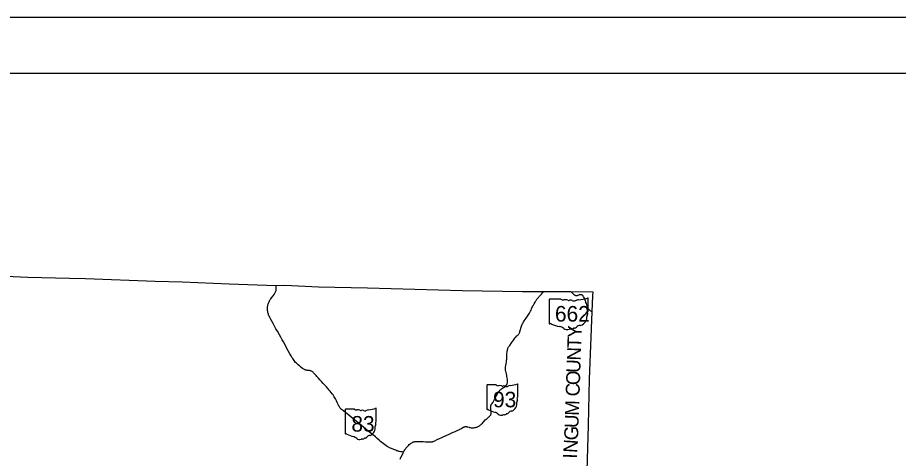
# Model space of a CAD drawing. Extents: x 1913970 to 2287843, y 78841 to 799733.
# Drawn here: x 2161112 to 2224478, y 768018 to 799733 of the extents above; entities that cross this region are included whole.
import ezdxf

# ---------------------------------------------------------------- set-up
doc = ezdxf.new("R2010")
doc.units = 0
for name, color, linetype in [('GM_X_County', 7, 'Continuous'), ('GM_X_County_Text', 7, 'Continuous'), ('GM_X_State_Location', 7, 'Continuous'), ('GM_X_State_Route', 7, 'Continuous'), ('GM_X_State_Shield', 7, 'Continuous'), ('SH_Border', 7, 'Continuous'), ('SH_Cut_Line', 7, 'Continuous')]:
    doc.layers.add(name, color=color, linetype=linetype)

msp = doc.modelspace()

# ---------------------------------------------------------------- linework, layer by layer
at = {"layer": 'GM_X_County'}
msp.add_lwpolyline([(2160255, 781127), (2161838, 781046), (2164851, 780995), (2165985, 780969), (2171000, 780768), (2172957, 780727), (2176338, 780588), (2179692, 780466), (2180329, 780472), (2182770, 780366), (2186293, 780295), (2193090, 780093), (2197442, 780016), (2198976, 780038), (2200924, 780017), (2202494, 779994), (2202479, 779737), (2202424, 778558), (2202231, 773716), (2202153, 770412), (2201913, 762197)], dxfattribs=at)
at = {"layer": 'GM_X_State_Route'}
for points in [[(2188873, 768462), (2188775, 768480), (2188678, 768496), (2188586, 768511), (2188581, 768512), (2188534, 768522), (2188487, 768535), (2188440, 768551), (2188395, 768569), (2188320, 768602), (2188254, 768630), (2188229, 768641), (2188122, 768683), (2187938, 768750), (2187877, 768775), (2187833, 768796), (2187790, 768820), (2187748, 768845), (2187694, 768881), (2187615, 768940), (2187421, 769090), (2187230, 769244), (2187128, 769327), (2186989, 769441), (2186851, 769558), (2186708, 769679), (2186701, 769685), (2186524, 769832), (2186423, 769915), (2186220, 770082), (2186016, 770247), (2185825, 770402), (2185649, 770549), (2185560, 770622), (2185484, 770684), (2185357, 770787), (2185229, 770891), (2185089, 771005), (2184950, 771119), (2184694, 771324), (2184552, 771435), (2184423, 771536), (2184387, 771569), (2184353, 771604), (2184321, 771641), (2184291, 771680), (2184264, 771721), (2184231, 771777), (2184192, 771849), (2184099, 772041), (2184042, 772159), (2183979, 772292), (2183941, 772365), (2183892, 772451), (2183841, 772535), (2183804, 772590), (2183765, 772643), (2183657, 772787), (2183606, 772852), (2183532, 772935), (2183450, 773024), (2183325, 773162), (2183194, 773303), (2183102, 773402), (2182973, 773544), (2182852, 773676), (2182750, 773792), (2182647, 773906), (2182582, 773978), (2182541, 774024), (2182464, 774106), (2182400, 774176), (2182364, 774212), (2182323, 774247), (2182292, 774272), (2182266, 774287), (2182240, 774300), (2182219, 774309), (2182190, 774319), (2182159, 774327), (2182119, 774334), (2182071, 774339), (2181993, 774346), (2181945, 774350), (2181897, 774357), (2181849, 774368), (2181818, 774378), (2181772, 774394), (2181742, 774407), (2181699, 774429), (2181657, 774454), (2181617, 774482), (2181579, 774513), (2181492, 774588), (2181391, 774672), (2181291, 774756), (2181240, 774802), (2181230, 774811), (2181171, 774867), (2181115, 774927), (2181061, 774989), (2181000, 775065), (2180951, 775131), (2180905, 775198), (2180852, 775281), (2180785, 775393), (2180697, 775550), (2180588, 775752), (2180465, 775983), (2180403, 776098), (2180237, 776398), (2180185, 776486), (2180145, 776554), (2180047, 776734), (2179951, 776904), (2179805, 777161), (2179801, 777168), (2179701, 777350), (2179498, 777716), (2179300, 778070), (2179252, 778156), (2179223, 778216), (2179196, 778276), (2179165, 778350), (2179150, 778397), (2179132, 778459), (2179116, 778523), (2179105, 778587), (2179097, 778652), (2179091, 778717), (2179088, 778783), (2179089, 778821), (2179092, 778884), (2179098, 778945), (2179107, 778994), (2179121, 779057), (2179138, 779121), (2179158, 779183), (2179181, 779244), (2179200, 779289), (2179229, 779348), (2179260, 779406), (2179293, 779462), (2179320, 779503), (2179368, 779569), (2179490, 779723), (2179560, 779814), (2179598, 779868), (2179625, 779909), (2179650, 779952), (2179671, 779997), (2179689, 780043), (2179702, 780091), (2179712, 780139), (2179719, 780188), (2179722, 780238), (2179722, 780287), (2179718, 780336), (2179714, 780382), (2179707, 780418), (2179693, 780463)], [(2188873, 768462), (2188923, 768551), (2188962, 768623), (2188986, 768666), (2189012, 768708), (2189031, 768735), (2189048, 768758), (2189056, 768767), (2189117, 768834), (2189184, 768906), (2189203, 768925), (2189231, 768953), (2189291, 769009), (2189353, 769063), (2189392, 769094), (2189432, 769122), (2189474, 769148), (2189517, 769173), (2189547, 769187), (2189578, 769199), (2189602, 769207), (2189625, 769214), (2189657, 769221), (2189690, 769226), (2189739, 769230), (2189789, 769231), (2189969, 769227), (2190117, 769224), (2190232, 769223), (2190298, 769222), (2190445, 769215), (2190543, 769211), (2190707, 769205), (2190805, 769203), (2190854, 769205), (2190903, 769209), (2190951, 769216), (2190983, 769224), (2191014, 769234), (2191059, 769252), (2191133, 769287), (2191294, 769369), (2191456, 769448), (2191575, 769503), (2191768, 769593), (2191949, 769672), (2192219, 769791), (2192309, 769831), (2192459, 769898), (2192482, 769908), (2192593, 769958), (2192774, 770037), (2192849, 770070), (2192893, 770090), (2192936, 770113), (2192993, 770146), (2193132, 770233), (2193176, 770258), (2193203, 770270), (2193226, 770279), (2193253, 770289), (2193284, 770296), (2193313, 770301), (2193331, 770303), (2193351, 770304), (2193385, 770304), (2193411, 770302), (2193432, 770299), (2193454, 770295), (2193499, 770283), (2193600, 770254), (2193630, 770248), (2193677, 770237), (2193737, 770228), (2193802, 770222), (2193851, 770220), (2193905, 770221), (2193946, 770223), (2193997, 770230), (2194044, 770240), (2194092, 770253), (2194138, 770269), (2194198, 770294), (2194242, 770314), (2194285, 770339), (2194331, 770367), (2194381, 770400), (2194419, 770430), (2194456, 770462), (2194492, 770495), (2194550, 770554), (2194682, 770700), (2194761, 770783), (2194820, 770840), (2194858, 770873), (2194909, 770914), (2194974, 770964), (2195021, 771004), (2195060, 771038), (2195092, 771071), (2195116, 771099), (2195134, 771123), (2195151, 771151), (2195162, 771175), (2195169, 771195), (2195179, 771226), (2195183, 771257), (2195185, 771286), (2195185, 771310), (2195183, 771342), (2195179, 771378), (2195166, 771453), (2195152, 771550), (2195148, 771599), (2195145, 771664), (2195147, 771713), (2195153, 771763), (2195159, 771795), (2195168, 771827), (2195179, 771858), (2195192, 771888), (2195208, 771917), (2195227, 771946), (2195248, 771974), (2195298, 772037), (2195328, 772074), (2195357, 772114), (2195383, 772156), (2195405, 772199), (2195425, 772244), (2195461, 772335), (2195485, 772392), (2195508, 772441), (2195537, 772499), (2195577, 772571), (2195682, 772757), (2195706, 772799), (2195724, 772826), (2195745, 772853), (2195777, 772890), (2195812, 772924), (2195852, 772957), (2195932, 773014), (2196064, 773111), (2196184, 773198), (2196220, 773229), (2196245, 773252), (2196267, 773275), (2196283, 773293), (2196293, 773307), (2196306, 773328), (2196320, 773357), (2196332, 773386), (2196342, 773417), (2196349, 773449), (2196353, 773481), (2196356, 773529), (2196356, 773578), (2196353, 773644), (2196345, 773725), (2196333, 773805), (2196316, 773913), (2196302, 773993), (2196277, 774105), (2196232, 774283), (2196224, 774330), (2196217, 774379), (2196212, 774429), (2196212, 774480), (2196212, 774543), (2196217, 774611), (2196230, 774692), (2196252, 774821), (2196278, 774966), (2196283, 775000), (2196287, 775030), (2196294, 775089), (2196298, 775146), (2196300, 775225), (2196305, 775469), (2196314, 775569), (2196322, 775650), (2196330, 775725), (2196346, 775816), (2196359, 775862), (2196372, 775910), (2196392, 775956), (2196414, 776001), (2196439, 776044), (2196469, 776090), (2196514, 776152), (2196640, 776323), (2196716, 776430), (2196781, 776525), (2196838, 776605), (2196877, 776658), (2196919, 776708), (2196953, 776744), (2197036, 776827), (2197083, 776871), (2197116, 776907), (2197136, 776932), (2197165, 776971), (2197192, 777013), (2197215, 777057), (2197235, 777100), (2197252, 777145), (2197276, 777224), (2197345, 777460), (2197366, 777523), (2197393, 777600), (2197416, 777660), (2197445, 777722), (2197474, 777779), (2197517, 777850), (2197562, 777921), (2197690, 778111), (2197839, 778325), (2197930, 778461), (2197964, 778517), (2197989, 778560), (2198016, 778618), (2198050, 778694), (2198083, 778769), (2198116, 778844), (2198149, 778917), (2198173, 778966), (2198188, 778994), (2198219, 779048), (2198264, 779128), (2198344, 779259), (2198397, 779344), (2198423, 779385), (2198477, 779466), (2198535, 779546), (2198578, 779599), (2198619, 779649), (2198696, 779732), (2198797, 779841), (2198871, 779924), (2198917, 779974), (2198977, 780035)], [(2202425, 778555), (2202388, 778576), (2202348, 778603), (2202322, 778624), (2202285, 778656), (2202255, 778689), (2202223, 778728), (2202194, 778766), (2202168, 778808), (2202147, 778848), (2202128, 778893), (2202066, 779059), (2202028, 779163), (2202000, 779241), (2201985, 779292), (2201974, 779337), (2201955, 779413), (2201947, 779441), (2201939, 779461), (2201924, 779492), (2201909, 779521), (2201835, 779648), (2201809, 779689), (2201790, 779716), (2201779, 779729), (2201767, 779741), (2201755, 779752), (2201742, 779762), (2201727, 779771), (2201713, 779778), (2201697, 779785), (2201681, 779790), (2201665, 779794), (2201649, 779797), (2201633, 779798), (2201614, 779799), (2201599, 779798), (2201583, 779797), (2201567, 779795), (2201544, 779789), (2201517, 779781), (2201458, 779756), (2201427, 779743), (2201396, 779731), (2201368, 779724), (2201351, 779720), (2201336, 779718), (2201320, 779717), (2201304, 779718), (2201288, 779720), (2201273, 779723), (2201258, 779728), (2201244, 779733), (2201230, 779740), (2201215, 779748), (2201199, 779758), (2201180, 779774), (2201163, 779787), (2200925, 780014)], [(2188627, 767954), (2188634, 767973), (2188652, 768018), (2188669, 768052)], [(2188669, 768052), (2188682, 768076), (2188793, 768292), (2188847, 768408), (2188873, 768462)]]:
    msp.add_lwpolyline(points, dxfattribs=at)
at = {"layer": 'GM_X_State_Shield'}
for p, q in [((2199356, 779442), (2199356, 777741)), ((2200204, 779471), (2199383, 779471)), ((2202158, 778624), (2202158, 779514)), ((2202157, 778624), (2202158, 778624)), ((2194861, 773275), (2194861, 771573)), ((2195539, 773304), (2194883, 773304)), ((2197102, 772456), (2197102, 773346)), ((2197102, 772456), (2197102, 772456)), ((2184672, 771526), (2184672, 769824)), ((2185351, 771555), (2184694, 771555)), ((2186914, 770707), (2186914, 771597)), ((2186913, 770707), (2186914, 770707))]:
    msp.add_line(p, q, dxfattribs=at)
for centre, radius, start, end in [((2194887, 773278), 26, 98.1301, 188.1301), ((2195696, 773501), 252, 231.61951, 271.11188), ((2195779, 772349), 904, 80.48669, 94.98827), ((2195985, 773287), 72.7, 219.79206, 297.10237), ((2196091, 773090), 151, 54.46668, 119.14113), ((2196286, 773360), 182, 233.85621, 294.82819), ((2196607, 772784), 478, 97.34618, 120.76885), ((2196304, 775623), 2377, 275.84447, 288.90645), ((2197077, 773350), 25, 351.86209, 97.738), ((2197097, 772391), 38.6, 107.94398, 210.33697), ((2197076, 772453), 26.7, 289.60381, 7.73413), ((2196437, 771971), 595, 292.30889, 8.98584), ((2197192, 772084), 169, 136.8065, 186.92959), ((2196851, 772278), 232, 340.03296, 23.64957), ((2184698, 771529), 26, 98.1301, 188.1301), ((2185507, 771752), 252, 231.61951, 271.11188), ((2185590, 770600), 904, 80.48669, 94.98827), ((2185796, 771538), 72.7, 219.79206, 297.10237), ((2185902, 771341), 151, 54.46668, 119.14113), ((2186097, 771611), 182, 233.85621, 294.82819), ((2186418, 771035), 478, 97.34618, 120.76885), ((2186115, 773874), 2377, 275.84447, 288.90645), ((2186889, 771601), 25, 351.86209, 97.738), ((2194887, 771570), 26.2, 171.95839, 258.30661), ((2194891, 771744), 200, 267.33899, 280.60386), ((2194932, 771475), 72.1, 29.74838, 93.27175), ((2195842, 773004), 1716, 240.41292, 257.1985), ((2195330, 770809), 537, 47.18416, 75.83597), ((2195911, 771467), 341, 230.70037, 286.29184), ((2196108, 770879), 280, 85.69512, 111.20995), ((2196133, 771339), 182, 268.77702, 315.54927), ((2196297, 771175), 51.1, 65.75173, 132.64842), ((2196275, 771409), 192, 282.87319, 323.27711), ((2196688, 771096), 326, 94.40312, 142.57675), ((2186908, 770642), 38.6, 107.94398, 210.33697), ((2186662, 770529), 232, 340.03296, 23.64957), ((2186887, 770704), 26.7, 289.60381, 7.73413), ((2186248, 770222), 595, 292.30889, 8.98584), ((2187003, 770335), 169, 136.8065, 186.92959), ((2184698, 769821), 26.2, 171.95839, 258.30661), ((2184702, 769995), 200, 267.33899, 280.60386), ((2184743, 769726), 72.1, 29.74838, 93.27175), ((2185653, 771255), 1716, 240.41292, 257.1985), ((2185141, 769060), 537, 47.18416, 75.83597), ((2185722, 769718), 341, 230.70037, 286.29184), ((2185919, 769130), 280, 85.69512, 111.20995), ((2185944, 769590), 182, 268.77702, 315.54927), ((2186108, 769426), 51.1, 65.75173, 132.64842), ((2186086, 769660), 192, 282.87319, 323.27711), ((2186499, 769347), 326, 94.40312, 142.57675)]:
    msp.add_arc(centre, radius, start, end, dxfattribs=at)
for centre, major_axis, start_param, end_param in [((2199388, 779446), (32.5, 0), 1.712693, 3.28349), ((2200399, 779669), (315, 0), 4.042523, 4.731795), ((2200504, 778516), (1130, 0), 1.404758, 1.657858), ((2200760, 779455), (90.8, 0), 3.836095, 5.185415), ((2200894, 779258), (189, 0), 0.950623, 2.079405), ((2201539, 778952), (598, 0), 1.699011, 2.107814), ((2201160, 781791), (2971, 0), 4.814394, 5.042369), ((2202126, 779517), (31.2, 0), 6.141152, 7.989035), ((2201137, 779528), (227, 0), 4.081561, 5.145723), ((2201326, 778138), (743, 0), 5.101752, 6.440018), ((2202269, 778251), (211, 0), 2.387724, 3.262537), ((2202150, 778558), (48.3, 0), 1.883978, 3.671073), ((2201843, 778446), (290, 0), 5.934695, 6.695948), ((2202124, 778620), (33.4, 0), 5.05454, 6.418171), ((2199388, 777737), (32.7, 0), 3.00124, 4.508301), ((2199393, 777911), (250, 0), 4.665946, 4.897461), ((2199444, 777643), (90.1, 0), 0.519207, 1.627899), ((2200582, 779171), (2146, 0), 4.195997, 4.488961), ((2199942, 776977), (671, 0), 0.823519, 1.323587), ((2201639, 777263), (407, 0), 1.647645, 2.488434), ((2200668, 777634), (426, 0), 4.026481, 4.996735), ((2200914, 777046), (350, 0), 1.495662, 1.94098), ((2200946, 777507), (227, 0), 4.691044, 5.507374), ((2201151, 777342), (63.9, 0), 1.147584, 2.315152), ((2201124, 777576), (240, 0), 4.937069, 5.64225)]:
    msp.add_ellipse(centre, major_axis=major_axis, ratio=0.8, start_param=start_param, end_param=end_param, dxfattribs=at)
at = {"layer": 'SH_Border'}
msp.add_lwpolyline([(2027843, 795733), (2283843, 795733), (2283843, 627733), (2027843, 627733)], close=True, dxfattribs=at)
at = {"layer": 'SH_Cut_Line'}
msp.add_lwpolyline([(2015843, 623733), (2287843, 623733), (2287843, 799733), (2015843, 799733)], close=True, dxfattribs=at)

# ---------------------------------------------------------------- texts
at = {"layer": 'GM_X_County_Text'}
for s, rotation, p in [('Y', 88.06606, (2201677, 776676)), ('T', 88.06338, (2201651, 775929)), ('N', 88.06493, (2201622, 775045)), ('U', 88.06624, (2201592, 774161)), ('O', 88.06549, (2201562, 773277)), ('C', 88.06443, (2201534, 772464)), ('M', 88.06467, (2201487, 771074)), ('U', 88.05623, (2201458, 770190)), ('G', 87.8269, (2201424, 769302)), ('N', 86.33514, (2201366, 768391)), ('I', 88.18534, (2201353, 767990))]:
    msp.add_text(s, height=1000, rotation=rotation, dxfattribs=at).set_placement(p)
at = {"layer": 'GM_X_State_Location'}
for s, p in [('s', (2201882, 779449)), ('r', (2201882, 779449)), ('s', (2195541, 772387)), ('r', (2195541, 772387)), ('s', (2185778, 770328)), ('r', (2185778, 770328))]:
    msp.add_text(s, height=1, dxfattribs=at).set_placement(p)
for s, p in [('662', (2201529, 779376)), ('93', (2195290, 772314)), ('83', (2185526, 770255))]:
    msp.add_text(s, height=1, rotation=0.00001, dxfattribs=at).set_placement(p)
at = {"layer": 'GM_X_State_Shield'}
for s, p in [('662', (2199772, 777861)), ('93', (2195317, 771693)), ('83', (2185128, 769944))]:
    msp.add_text(s, height=1120.7, dxfattribs=at).set_placement(p)

doc.saveas('drawing.dxf')
